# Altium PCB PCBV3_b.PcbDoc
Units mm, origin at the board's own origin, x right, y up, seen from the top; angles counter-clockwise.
Board outline 25 x 50 mm, 2 copper layers (Top Layer, Bottom Layer); 34 components, 34 nets, 132 pads, 7 vias.
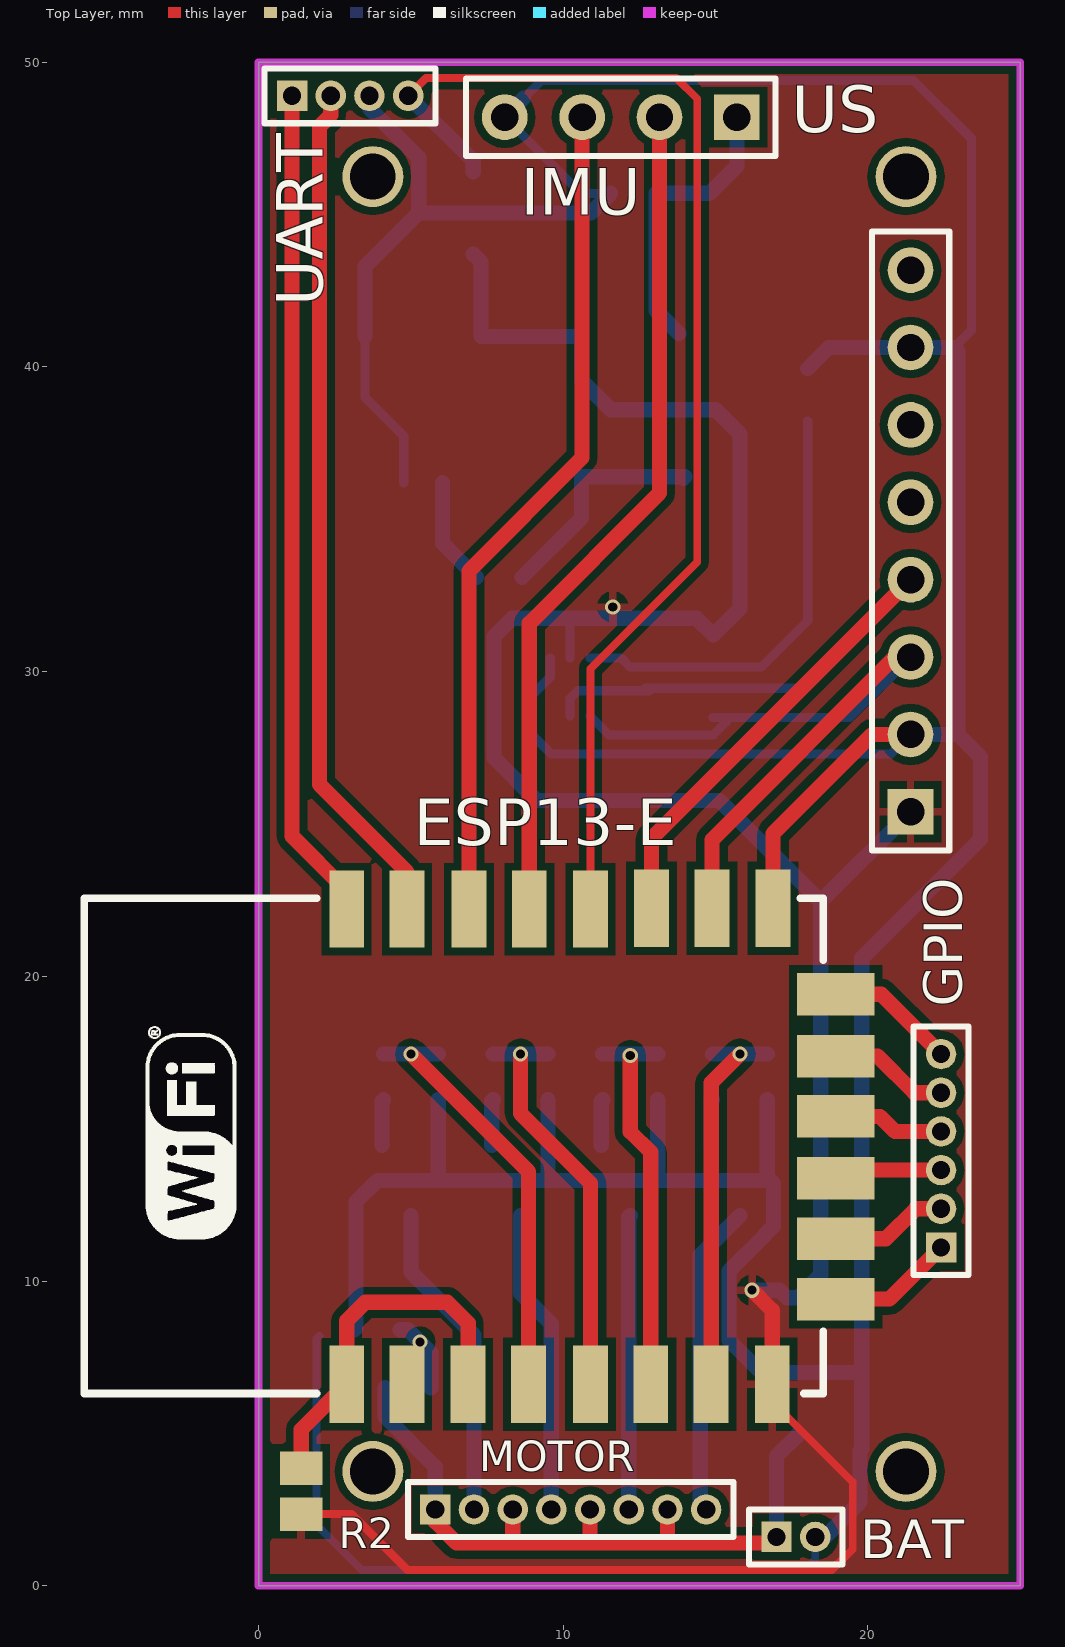
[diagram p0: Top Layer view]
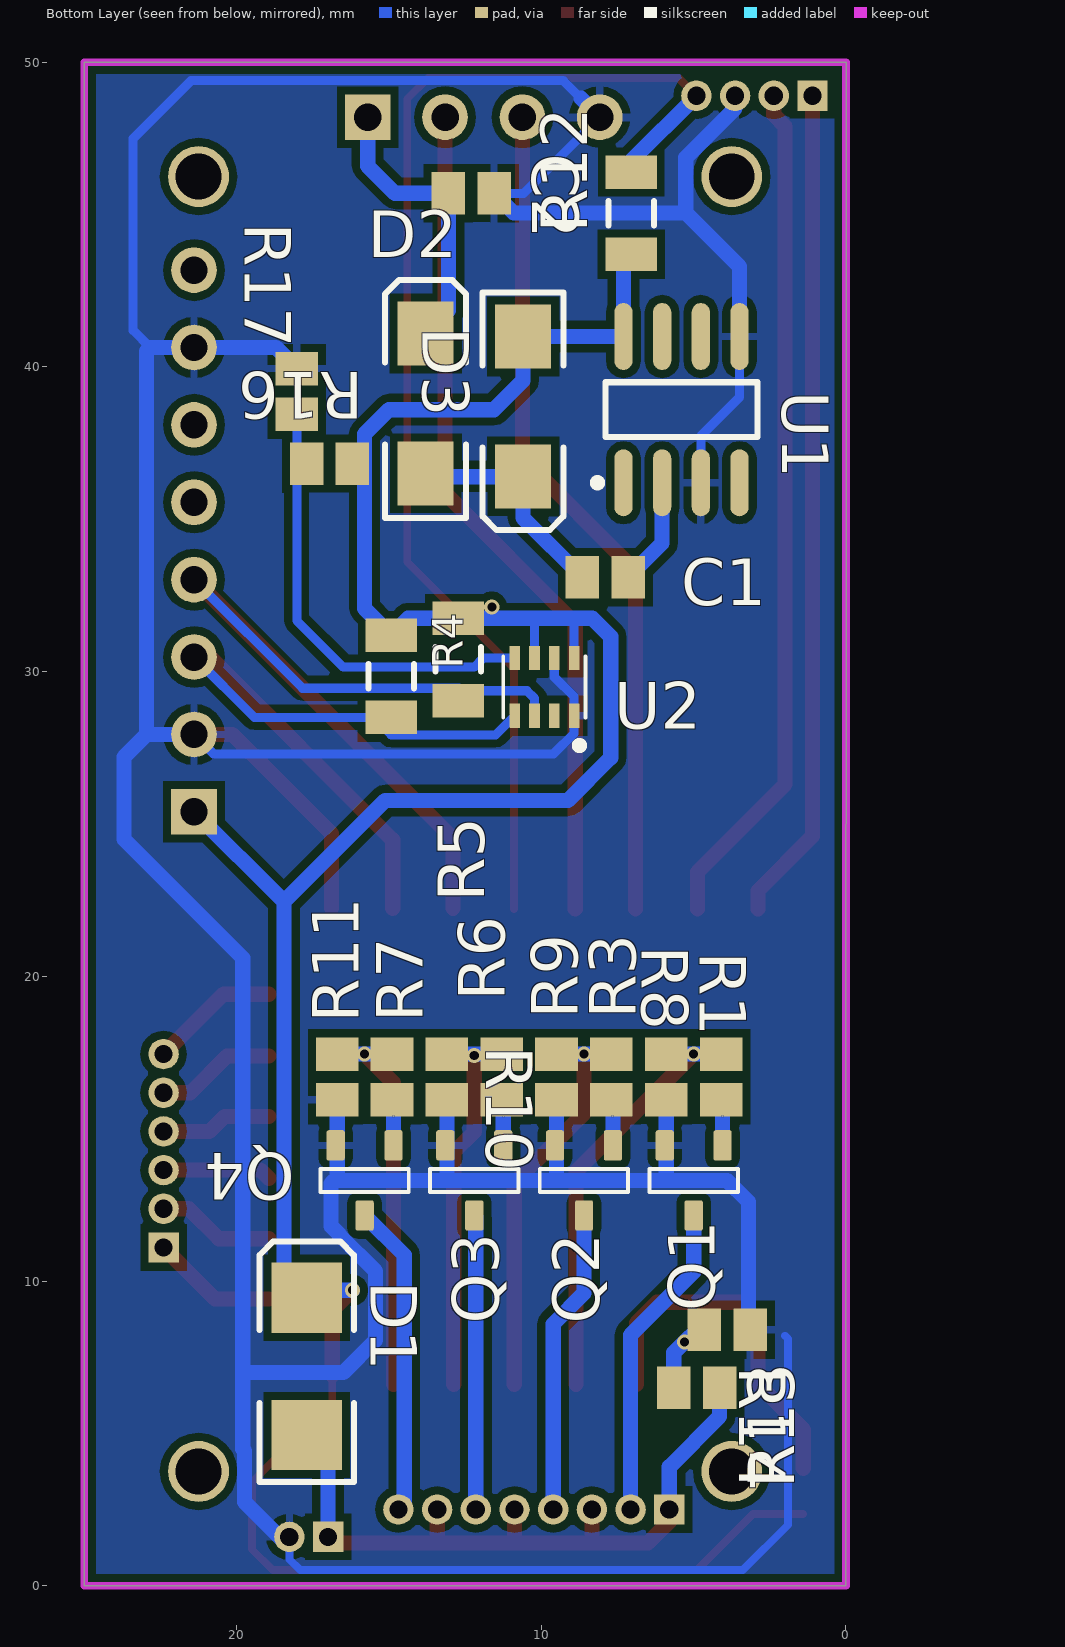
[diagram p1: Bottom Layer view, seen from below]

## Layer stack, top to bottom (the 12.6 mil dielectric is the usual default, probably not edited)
Top Solder: solder mask 0.0102, Solder Resist, Dk 3.5
Top Layer: signal copper 0.0356
Dielectric 1: dielectric 0.32, FR-4, Dk 4.8
Bottom Layer: signal copper 0.0356
Bottom Solder: solder mask 0.0102, Solder Resist, Dk 3.5

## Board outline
0,0 25,0 25,50 0,50

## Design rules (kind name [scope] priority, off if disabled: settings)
Clearance [All] p1: gap=0.256
PolygonConnect [All] p1: connectstyle=Relief reliefconductorwidth=0.254 reliefentries=4 polygonreliefangle="90 Angle" airgapwidth=0.254
RoutingVias [All] p1: holewidth=0.711 width=1.27 viastyle="Through Hole" minholewidth=0.711 minwidth=1.27 maxholewidth=0.711 maxwidth=1.27
SolderMaskExpansion [All] p1: expansion=0.102
Width [All] p1: maxlimit=2 minlimit=0.256 preferedwidth=0.5
30 further rules are at their usual default settings.

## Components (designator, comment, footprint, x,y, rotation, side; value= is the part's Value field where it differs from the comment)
BAT "Header 2" MHDR1X2 17,1.6 r0 top (schematic designator P1)
C1 "Cap" C0805 7.9,33.1 r0 bottom
C2 "Cap" C0805 12.3,45.7 r0 bottom
D1 "Diode 1N5402" DSO-C2/X2.3 17.7,7.2 r90 bottom
D2 "Diode 1N5402" DSO-C2/Z6.7 13.8,38.8 r90 bottom
D3 "Diode 1N5402" DSO-C2/Z6.7 10.6,38.7 r270 bottom
ESP13-E "ESP8266 ESP-12-E" "ESP8266 ESP-12-E B" 19.3,23.2 r90 top (schematic designator IC1)
GPIO "MHDR1X6" MHDR1X6 22.4,11.1 r90 top (schematic designator P1)
IMU "Header 8" HDR1X8 21.4,25.4 r90 top (schematic designator P5)
MOTOR "MHDR1X8" MHDR1X8 5.8,2.5 r0 top (schematic designator P3)
Q1 "MOSFET-N" SOT23-3 5,13.3 r270 bottom
Q2 "MOSFET-N" SOT23-3 8.6,13.3 r270 bottom
Q3 "MOSFET-N" SOT23-3 12.2,13.3 r270 bottom
Q4 "MOSFET-N" SOT23-3 15.8,13.3 r270 bottom
R1 "Res3" C0805 4.1,16.7 r270 bottom
R2 "Res3" C0805 1.4,3.1 r90 top
R3 "Res3" C0805 7.7,16.7 r270 bottom
R4 "Res3" C1206 14.925,29.85 r90 bottom
R5 "Res3" C1206 12.725,30.4 r90 bottom
R6 "Res3" C0805 11.3,16.7 r270 bottom
R7 "Res3" C0805 14.9,16.7 r270 bottom
R8 "Res3" C0805 5.9,16.7 r270 bottom
R9 "Res3" C0805 9.5,16.7 r270 bottom
R10 "Res3" C0805 13.1,16.7 r270 bottom
R11 "Res3" C0805 16.7,16.7 r270 bottom
R12 "Res3" C1206 7.05,45.05 r90 bottom
R13 "Res3" C0805 4.9,6.5 r0 bottom
R14 "Res3" C0805 3.9,8.4 r180 bottom
R16 "Res3" C0805 16.95,36.825 r180 bottom
R17 "Res3" C0805 18.025,39.2 r90 bottom
U1 "LMC7660IM" M08A_N 5.4,38.6 r90 bottom
U2 "BMP280" LGA-8_BMP280(Primary) 9.9,29.5 r270 bottom
UART "MHDR1X4" MHDR1X4 1.1,48.9 r0 top (schematic designator P2)
US "Header 4" HDR1X4 15.7,48.2 r180 top (schematic designator P4)

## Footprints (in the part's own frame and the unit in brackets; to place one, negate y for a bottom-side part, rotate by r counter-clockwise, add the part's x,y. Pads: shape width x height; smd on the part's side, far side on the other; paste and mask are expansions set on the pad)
C0805 [mm] "Chip Capacitor, Body 2.0x1.3mm, IPC High Density"
  rect 1.1x1.4 smd: 1(-0.75,0) 2(0.75,0)
  body extent -1.1,-0.72 1.1,0.72, height 1.4
C1206 [mm] "Chip Capacitor, Body 3.2x1.6mm, IPC High Density"
  rect 1.1x1.7 smd: 1(-1.35,0) 2(1.35,0)
  silkscreen extent -0.4,-0.75 0.4,0.75, body extent -1.7,-0.9 1.7,0.9, height 1.3
DSO-C2/X2.3 [mm] "DO-214-AA/SMB; 2 C-Bend Leads; Body 5.3 x 3.6 mm, inc. leads (LxW)"
  rect 2.3x2.3 smd: 1(-2.25,0) 2(2.25,0)
  silkscreen extent -3.8,-1.55 4.1,1.55
DSO-C2/Z6.7 [mm] "DO-214-AC/SMA; 2 C-Bend Leads; Body 5.3 x 2.6 mm, inc. leads (LxW)"
  rect 2.1x1.85 smd: 1(-2.3,0) 2(2.3,0)
  silkscreen extent -3.75,-1.33 4.05,1.33
"ESP8266 ESP-12-E B" [mil] "ESP8266 ESP-12-E"
  rect 100x45 smd: 1(-653,646) 2(-653,568) 3(-653,489) 4(-653,411) 5(-653,331) 6(-653,253) 7(-653,175) 8(-653,96) 15(-38,95) 16(-38,174) 17(-38,252) 18(-39,331) 19(-39,410) 20(-39,488) 21(-39,568) 22(-39,646)
  rect 55x100 smd: 9(-543,14) 10(-465,14) 11(-387,14) 12(-307,14) 13(-229,14) 14(-149,14)
  silkscreen extent -665,30 -25,985
HDR1X4 [mm] "Connector; Header; 4 Position"
  rect 1.5x1.5 hole 0.9: 1(0,0)
  round 1.5 hole 0.9: 2(2.54,0) 3(5.08,0) 4(7.62,0)
  silkscreen extent -1.27,-1.27 8.89,1.27
HDR1X8 [mm] "Connector; Header; 8 Position"
  rect 1.5x1.5 hole 0.9: 1(0,0)
  round 1.5 hole 0.9: 2(2.54,0) 3(5.08,0) 4(7.62,0) 5(10.16,0) 6(12.7,0) 7(15.24,0) 8(17.78,0)
  silkscreen extent -1.27,-1.27 19.05,1.27
LGA-8_BMP280(Primary) [mm]
  rect 0.8x0.35 smd paste-25.4 mask-25.4: 1(0.95,0.975) 2(0.95,0.325) 3(0.95,-0.325) 4(0.95,-0.975) 5(-0.95,-0.975) 6(-0.95,-0.325) 7(-0.95,0.325) 8(-0.95,0.975)
  silkscreen extent -1,-1.35 2.02,1.35
M08A_N [mm] "SOIC, 8-Leads, Body 4.9x3.9mm, Pitch 1.27mm, IPC Medium Density"
  oval 2.2x0.6 smd: 1(-2.4,1.905) 2(-2.4,0.635) 3(-2.4,-0.635) 4(-2.4,-1.905) 5(2.4,-1.905) 6(2.4,-0.635) 7(2.4,0.635) 8(2.4,1.905)
  silkscreen extent -2.52,-2.5 0.9,2.88, body extent -2,-2.5 2,2.5, height 1.75
MHDR1X2 [mm] "Connector; Header; 2 Position"
  rect 1x1 hole 0.6: 1(0,0)
  round 1 hole 0.6: 2(1.27,0)
  silkscreen extent -0.9,-0.9 2.17,0.9
MHDR1X4 [mm] "Connector; Header; 4 Position"
  rect 1x1 hole 0.6: 1(0,0)
  round 1 hole 0.6: 2(1.27,0) 3(2.54,0) 4(3.81,0)
  silkscreen extent -0.9,-0.9 4.71,0.9
MHDR1X6 [mm] "Connector; Header; 6 Position"
  rect 1x1 hole 0.6: 1(0,0)
  round 1 hole 0.6: 2(1.27,0) 3(2.54,0) 4(3.81,0) 5(5.08,0) 6(6.35,0)
  silkscreen extent -0.9,-0.9 7.25,0.9
MHDR1X8 [mm] "Connector; Header; 8 Position"
  rect 1x1 hole 0.6: 1(0,0)
  round 1 hole 0.6: 2(1.27,0) 3(2.54,0) 4(3.81,0) 5(5.08,0) 6(6.35,0) 7(7.62,0) 8(8.89,0)
  silkscreen extent -0.9,-0.9 9.79,0.9
SOT23-3 [mm] "SOT23, 3 pin"
  round 0.5 on Mech15: 0(0,0)
  rrect25% 1x0.6 smd: 1(-1.15,0.95) 2(-1.15,-0.95) 3(1.15,0)
  silkscreen extent -0.38,-1.45 0.38,1.45, body extent -1.4,-1.45 1.4,1.45, height 1.29

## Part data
BAT: "Header, 2-Pin"
C1 C2: "Capacitor"
D1 D2 D3: "3 Amp General Purpose Rectifier"
GPIO: "Header, 6-Pin"
IMU MOTOR: "Header, 8-Pin"
Q1 Q2 Q3 Q4: "N-Channel MOSFET"
R1 R2 R3 R4 R5 R6 R7 R8 R9 R10 R11 R12 R13 R14 R16 R17: "Resistor"
U1: "Switched Capacitor Voltage Converter, 8-pin Narrow SOIC"
U2: "Barometro"
UART US: "Header, 4-Pin"

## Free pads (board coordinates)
  round 2 hole 1.5: 1(3.75,46.25) 2(21.25,46.25) 3(21.25,3.75) 4(3.75,3.75)

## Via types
v1: diameter 0.5, hole 0.3, Top Layer to Bottom Layer, 7 vias

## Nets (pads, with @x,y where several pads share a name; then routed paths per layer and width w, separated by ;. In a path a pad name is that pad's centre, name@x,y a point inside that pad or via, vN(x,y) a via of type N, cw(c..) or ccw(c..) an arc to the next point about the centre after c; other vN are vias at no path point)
5VCC: C2.2 D2.2 US.1 | length 9.5
  Bottom Layer w0.5: D2.2 13.05,41.85 C2.2 14.8,45.7 15.7,46.6 US.1
ADC: ESP13-E.2 R13.2 R14.1 | length 2.5
  Bottom Layer w0.5: R14.1 4.9,8.4 v1(5.3,8) 5.65,7.65 R13.2
BOOT: ESP13-E.18 R12.2 UART.4 | length 41.4
  Top Layer w0.256: UART.4 5.498,49.488 13.712,49.488 14.4,48.8 14.4,33.6 10.893,30.093 ESP13-E.18
  Bottom Layer w0.5: UART.4 7.05,46.76 R12.2
ECHO: ESP13-E.20 US.3 | length 27.5
  Top Layer w0.5: ESP13-E.20 6.905,33.305 10.62,37.02 US.3
GND: BAT.2 C2.1 ESP13-E.15 IMU.2 IMU.7 Q1.2 Q2.2 Q3.2 Q4.2 R8.2 R9.2 R10.2 R11.2 R14.2 R17.2 U1.3 U1.5 U2.1 U2.7 UART.3 US.4 | length 186.2
  Top Layer w0.5: ESP13-E.15 16.887,24.687 20.14,27.94 IMU.2
  Bottom Layer w0.256: 2,8.2 1.9,8.1 1.9,2 3.388,0.512 17.912,0.512 18.27,0.87 18.27,1.4 BAT.2
  Bottom Layer w0.3: U1.5 3.495,39.005 4.765,37.735 U1.3 ; US.4 10.58,45.7 C2.1 ; 8.7,48.82 9.28,49.4 21.5,49.4 23.4,47.5 23.4,41.2 22.84,40.64 ; U2.7 9.575,29.825 8.925,29.175 U2.1 8.925,27.975 9.6,27.3 20.76,27.3 IMU.2
  Bottom Layer w0.5: R14.2 3.2,8.45 3.2,12.6 3.9,13.3 5.9,13.3 ; U1.5 3.495,43.295 5.256,45.056 ; UART.3 3.64,48.49 5.256,46.874 5.256,45.056 ; R8.2 5.9,13.3 ; US.4@7.774,47.894 US.4 ; US.4@8.08,47.88 US.4 ; 8.7,48.82 US.4 ; R9.2 9.5,13.4 9.6,13.3 ; C2.1 10.906,45.056 5.256,45.056 ; R10.2 13.1,13.4 13.2,13.3 ; 16.7,13.5 R11.2 ; R17.2 18.715,40.64 IMU.7 22.84,40.64 22.96,40.52 22.96,27.94 ; BAT.2@18.27,1.4 18.4,1.4 19.744,2.744 19.744,4.43 19.8,4.486 19.8,7 ; IMU.2 22.96,27.94 ; 5.9,13.3 9.6,13.3 ; 9.6,13.3 13.2,13.3 ; 13.2,13.3 16.8,13.3 16.9,13.2 16.9,11.8 16.606,11.506 16.606,11.484 15.444,10.322 15.444,8.056 16.5,7 19.8,7 ; 19.8,7 19.8,20.6 23.7,24.5 23.7,27.2 22.96,27.94
GPIO_1: ESP13-E.9 GPIO.1 | length 4.2
  Top Layer w0.5: ESP13-E.9 20.708,9.408 GPIO.1
GPIO_2: ESP13-E.10 GPIO.2 | length 3.9
  Top Layer w0.5: ESP13-E.10 20.589,11.389 21.57,12.37 GPIO.2
GPIO_3: ESP13-E.11 GPIO.3 | length 3.6
  Top Layer w0.5: ESP13-E.11 19.214,13.64 GPIO.3
GPIO_4: ESP13-E.12 GPIO.4 | length 3.7
  Top Layer w0.5: ESP13-E.12 20.398,15.402 20.89,14.91 GPIO.4
GPIO_5: ESP13-E.13 GPIO.5 | length 4
  Top Layer w0.5: ESP13-E.13 20.317,17.383 21.52,16.18 GPIO.5
GPIO_6: ESP13-E.14 GPIO.6 | length 4.3
  Top Layer w0.5: ESP13-E.14 20.435,19.415 GPIO.6
I2C_SCL: ESP13-E.16 IMU.3 R4.1 U2.4 | length 23.7
  Top Layer w0.5: ESP13-E.16 14.88,24.48 20.88,30.48 IMU.3
  Bottom Layer w0.3: U2.4 11.5,27.925 14.925,27.925 R4.1@15.35,28.35 ; R4.1 19.42,28.5 IMU.3 IMU.3@21.23,30.65
I2C_SDA: ESP13-E.17 IMU.4 R5.1 U2.3 | length 27.8
  Top Layer w0.5: ESP13-E.17 12.899,24.519 IMU.4
  Bottom Layer w0.3: U2.3 10.225,29.125 10.475,29.375 R5.1@12.825,29.375 ; R5.1@12.7,29.425 12.7,29.456 17.836,29.456 IMU.4
NetC1_1: C1.1 U1.2 | length 3.6
  Bottom Layer w0.5: U1.2 6.035,34.215 C1.1
NetC1_2: C1.2 D2.1 D3.2 | length 7.5
  Bottom Layer w0.5: C1.2 10.6,35.05 D3.2 13.9,36.4 13.95,36.35 D2.1@14,36.4
NetESP13-E_1: ESP13-E.1 ESP13-E.3 R2.2 | length 12
  Top Layer w0.5: R2.2 1.4,5.122 ESP13-E.1 2.892,8.692 3.5,9.3 6.2,9.3 6.879,8.621 ESP13-E.3
NetMOTOR_2: MOTOR.2 Q1.3 | length 10.5
  Bottom Layer w0.5: Q1.3 5,10.3 7.07,8.23 MOTOR.2
NetMOTOR_4: MOTOR.4 Q2.3 | length 10.1
  Bottom Layer w0.5: Q2.3 8.6,9.6 9.61,8.59 MOTOR.4
NetMOTOR_6: MOTOR.6 Q3.3 | length 9.7
  Bottom Layer w0.5: MOTOR.6 12.15,12.1 Q3.3
NetMOTOR_8: MOTOR.8 Q4.3 | length 10.3
  Bottom Layer w0.5: MOTOR.8 14.5,2.69 14.5,10.85 Q4.3
NetQ1_2: Q1.1 R1.2 | length 1.5
  Bottom Layer w0.5: Q1.1 4.05,15.9 R1.2
NetQ2_2: Q2.1 R3.2 | length 1.5
  Bottom Layer w0.5: Q2.1 7.65,15.9 R3.2
NetQ3_2: Q3.1 R6.2 | length 1.5
  Bottom Layer w0.5: Q3.1 11.25,15.9 R6.2
NetQ4_2: Q4.1 R7.2 | length 1.5
  Bottom Layer w0.5: Q4.1 14.85,15.9 R7.2
NetR16_1: R16.1 R17.1 U2.5 | length 14.5
  Bottom Layer w0.3: U2.5 11.9,30.45 12.2,30.15 16.5,30.15 18.025,31.675 R17.1@18.025,38.225
PWM0: ESP13-E.4 R1.1 R8.1 | length 14.2
  Top Layer w0.5: v1(5,17.45) 8.861,13.589 ESP13-E.4
  Bottom Layer w0.5: R1.1 v1(5,17.45) R8.1
PWM1: ESP13-E.5 R3.1 R9.1 | length 13.6
  Top Layer w0.5: v1(8.6,17.45) 8.6,15.5 10.893,13.207 ESP13-E.5
  Bottom Layer w0.5: R3.1 v1(8.6,17.45) R9.1
PWM2: ESP13-E.6 R6.1 R10.1 | length 12.9
  Top Layer w0.5: v1(12.2,17.4) 12.2,14.9 12.874,14.226 ESP13-E.6
  Bottom Layer w0.5: R6.1 R10.1
PWM3: ESP13-E.7 R7.1 R11.1 | length 13
  Top Layer w0.5: ESP13-E.7 14.855,16.505 v1(15.8,17.45)
  Bottom Layer w0.5: R7.1 v1(15.8,17.45) R11.1
RX: ESP13-E.21 UART.2 | length 28
  Top Layer w0.5: UART.2 2.37,48.27 2,47.9 2,26.3 4.873,23.427 ESP13-E.21
TRIGER: ESP13-E.19 US.2 | length 27.8
  Top Layer w0.5: ESP13-E.19 8.886,31.586 13.16,35.86 US.2
TX: ESP13-E.22 UART.1 | length 27.4
  Top Layer w0.5: UART.1 1.1,24.6 2.892,22.808 ESP13-E.22
VCC: D1.2 D3.1 ESP13-E.8 IMU.1 R2.1 R4.2 R5.2 R12.1 R16.2 U1.8 U2.6 U2.8 | length 95.5
  Top Layer w0.256: R2.1 3.05,2.35 4.888,0.512 18.812,0.512 19.5,1.2 19.5,3.4 16.862,6.038 ESP13-E.8 ESP13-E.8@16.862,6.9
  Top Layer w0.5: v1(16.2,9.7) 16.862,9.038 ESP13-E.8@16.862,6.9
  Bottom Layer w0.3: U2.8 8.925,31.75 ; 10.2,31.75 10.225,31.725 U2.6
  Bottom Layer w0.5: R12.1 7.305,43.445 U1.8 D3.1 10.6,39.55 11.55,38.6 15,38.6 15.8,37.8 15.8,32.075 R4.2 14.375,31.75 R5.2 10.2,31.75 8.925,31.75 8.325,31.75 7.725,31.15 7.725,27.175 9.125,25.775 15.125,25.775 18.45,22.45 ; v1(16.2,9.7) 17.1,9.7 17.35,9.45 D1.2 18.45,10.2 18.45,22.45 ; IMU.1 18.45,22.45
  other v1: 11.625,32.125
VCC_BAT: BAT.1 D1.1 MOTOR.1 MOTOR.3 MOTOR.5 MOTOR.7 R13.1 | length 23.8
  Top Layer w0.5: MOTOR.1 5.8,2.1 6.5,1.4 8.3,1.4 ; MOTOR.3 8.34,1.44 8.3,1.4 ; MOTOR.5 10.88,1.48 10.8,1.4 ; MOTOR.7 13.42,1.42 13.4,1.4 ; BAT.1@17,1.4 13.4,1.4 ; 8.3,1.4 10.8,1.4 ; 10.8,1.4 13.4,1.4
  Bottom Layer w0.5: R13.1 4.15,5.55 5.8,3.9 MOTOR.1 ; BAT.1@17,1.4 17,4.25 D1.1
pads on no net: IMU.5 IMU.6 IMU.8 Q1.0 Q2.0 Q3.0 Q4.0 U1.1 U1.4 U1.6 U1.7 U2.2

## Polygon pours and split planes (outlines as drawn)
VCC on Top Layer "Plano_VCC" (solid, pour order 30): 0,50 25,50 25,0 0,0
GND on Bottom Layer "Plano_GND" (solid, pour order 32): 0,50 25,50 25,0 0,0

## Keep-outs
Keep-Out Layer:
  the board outline again, w0.256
